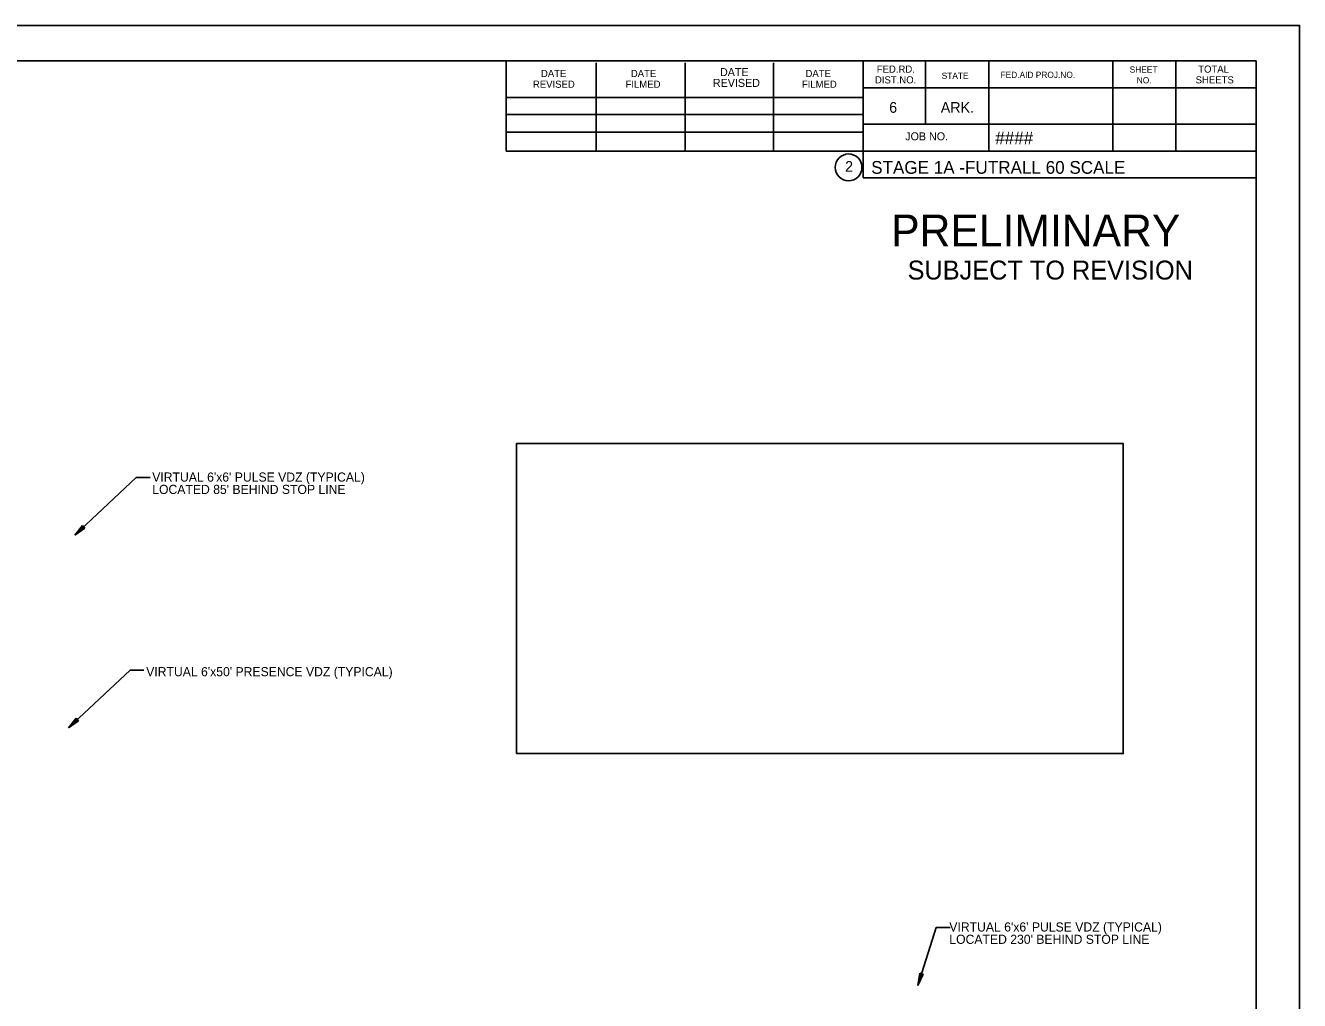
# Model space of a CAD drawing. Extents: x 662183 to 663183, y 642099 to 642739.
# Drawn here: x 662763.4 to 663182.7, y 642418.5 to 642739.3 of the extents above; entities that cross this region are included whole.
import ezdxf

# ---------------------------------------------------------------- set-up
doc = ezdxf.new("R2010")
doc.units = 0
for name, color, linetype in [('R_Border', 7, 'Continuous'), ('R_Border Prem', 7, 'Continuous'), ('R_No Plot', 7, 'Continuous'), ('T_Drafting', 7, 'Continuous')]:
    doc.layers.add(name, color=color, linetype=linetype)

msp = doc.modelspace()

# ---------------------------------------------------------------- linework, layer by layer
at = {"layer": 'R_Border'}
for p, q in [((662219.86, 642727.62), (663168.4, 642727.62)), ((662921.62, 642697.98), (662921.62, 642727.62)), ((662951.2, 642697.98), (662951.2, 642727.02)), ((662980.48, 642697.98), (662980.48, 642727.02)), ((663009.52, 642697.98), (663009.52, 642727.02)), ((663039.1, 642727.62), (663039.1, 642689.22)), ((663059.62, 642727.62), (663059.62, 642706.8)), ((663080.44, 642727.62), (663080.44, 642697.98)), ((663121.18, 642727.62), (663121.18, 642697.98)), ((663142, 642727.62), (663142, 642697.98)), ((663168.4, 642111.24), (663168.4, 642727.62)), ((663168.4, 642718.8), (663039.1, 642718.8)), ((663168.4, 642718.86), (663168.4, 642718.86)), ((662921.62, 642715.56), (663039.1, 642715.56)), ((662921.62, 642709.98), (663039.1, 642709.98)), ((663168.4, 642706.8), (663039.1, 642706.8)), ((663047.98, 642706.8), (663168.4, 642706.8)), ((662921.62, 642697.98), (662921.62, 642704.16)), ((662921.62, 642704.16), (663039.1, 642704.16)), ((663168.4, 642697.98), (662921.62, 642697.98)), ((663039.1, 642689.22), (663168.4, 642689.22))]:
    msp.add_line(p, q, dxfattribs=at)
msp.add_circle((663034.26, 642692.62), 4.4, dxfattribs=at)
at = {"layer": 'R_No Plot'}
msp.add_line((662182.66, 642739.3), (663182.66, 642739.3), dxfattribs=at)
msp.add_lwpolyline([(662182.64, 642739.3), (663182.66, 642739.3), (663182.66, 642099.29), (662182.64, 642099.29)], close=True, dxfattribs=at)
at = {"layer": 'T_Drafting'}
for p, q in [((662799.85, 642590.61), (662779.59, 642571.66)), ((662804.44, 642590.61), (662799.85, 642590.61)), ((662782.1, 642574.83), (662779.59, 642571.66)), ((662782.92, 642573.95), (662779.59, 642571.66)), ((662782.17, 642574.76), (662780.08, 642572.11)), ((662782.85, 642574.03), (662780.08, 642572.11)), ((662782.24, 642574.68), (662780.58, 642572.58)), ((662782.78, 642574.1), (662780.58, 642572.58)), ((662782.31, 642574.61), (662781.07, 642573.04)), ((662782.71, 642574.17), (662781.07, 642573.04)), ((662782.38, 642574.53), (662781.56, 642573.5)), ((662782.64, 642574.25), (662781.56, 642573.5)), ((662782.45, 642574.46), (662782.05, 642573.96)), ((662782.58, 642574.32), (662782.05, 642573.96)), ((662782.92, 642573.95), (662782.1, 642574.83)), ((662797.79, 642527.14), (662777.53, 642508.19)), ((662802.38, 642527.14), (662797.79, 642527.14)), ((662780.04, 642511.36), (662777.53, 642508.19)), ((662780.86, 642510.48), (662777.53, 642508.19)), ((662780.11, 642511.29), (662778.02, 642508.65)), ((662780.79, 642510.56), (662778.02, 642508.65)), ((662780.18, 642511.21), (662778.52, 642509.12)), ((662780.72, 642510.63), (662778.52, 642509.12)), ((662780.25, 642511.14), (662779.01, 642509.57)), ((662780.65, 642510.71), (662779.01, 642509.57)), ((662780.32, 642511.07), (662779.5, 642510.03)), ((662780.58, 642510.78), (662779.5, 642510.03)), ((662780.39, 642510.99), (662779.99, 642510.49)), ((662780.52, 642510.85), (662779.99, 642510.49)), ((662780.86, 642510.48), (662780.04, 642511.36)), ((663063.07, 642442.53), (663057.07, 642423.5)), ((663067.66, 642442.53), (663063.07, 642442.53)), ((663057.7, 642427.5), (663057.07, 642423.5)), ((663058.84, 642427.14), (663057.07, 642423.5)), ((663057.79, 642427.47), (663057.27, 642424.14)), ((663058.75, 642427.17), (663057.27, 642424.14)), ((663057.89, 642427.44), (663057.47, 642424.8)), ((663058.65, 642427.2), (663057.47, 642424.8)), ((663057.98, 642427.41), (663057.67, 642425.43)), ((663058.55, 642427.23), (663057.67, 642425.43)), ((663058.84, 642427.14), (663057.7, 642427.5)), ((663058.08, 642427.38), (663057.88, 642426.08)), ((663058.45, 642427.26), (663057.88, 642426.08)), ((663058.18, 642427.35), (663058.08, 642426.71)), ((663058.36, 642427.29), (663058.08, 642426.71))]:
    msp.add_line(p, q, dxfattribs=at)
msp.add_lwpolyline([(662924.98, 642499.74), (663124.64, 642499.74), (663124.64, 642601.74), (662924.98, 642601.74)], close=True, dxfattribs=at)

# ---------------------------------------------------------------- texts
at = {"layer": 'R_Border'}
for s, height, p in [('DATE', 2.346, (662933.02, 642722.34)), ('DATE', 2.346, (662962.6, 642722.34)), ('DATE', 2.638, (662991.94, 642722.64)), ('DATE', 2.346, (663020.08, 642722.34)), ('DIST.NO.', 2.346, (663042.94, 642720.24)), ('FED.RD.', 2.346, (663043.54, 642723.78)), ('STATE', 2.052, (663064.9, 642721.74)), ('FED.AID PROJ.NO.', 2.052, (663084.28, 642722.04)), ('SHEET', 2.052, (663126.76, 642723.78)), ('SHEETS', 2.346, (663148.48, 642720.24)), ('TOTAL', 2.346, (663149.32, 642723.78)), ('REVISED', 2.346, (662930.38, 642718.8)), ('FILMED', 2.346, (662960.86, 642718.8)), ('REVISED', 2.638, (662989.6, 642719.1)), ('FILMED', 2.346, (663018.88, 642718.8)), ('NO.', 2.052, (663129.1, 642720.24)), ('6', 3.52, (663047.62, 642710.58)), ('ARK.', 3.517, (663064.6, 642710.58)), ('JOB NO.', 2.638, (663052.9, 642701.52)), ('####', 4.2, (663082.53, 642700.19)), ('2', 3.52, (663033.11, 642691.16)), ('STAGE 1A -FUTRALL 60 SCALE', 4.2, (663041.69, 642690.51))]:
    msp.add_text(s, height=height, rotation=360, dxfattribs=at).set_placement(p)
at = {"layer": 'R_Border Prem'}
for s, height, p in [('PRELIMINARY', 10.5, (663048.26, 642666.61)), ('SUBJECT TO REVISION', 6.2253, (663053.68, 642655.72))]:
    msp.add_text(s, height=height, rotation=360, dxfattribs=at).set_placement(p)
at = {"layer": 'T_Drafting'}
for s, p in [("VIRTUAL 6'x6' PULSE VDZ (TYPICAL)", (662805.09, 642589.23)), ("LOCATED 85' BEHIND STOP LINE", (662805.09, 642585.17)), ("VIRTUAL 6'x50' PRESENCE VDZ (TYPICAL)", (662803.1, 642525.2)), ("VIRTUAL 6'x6' PULSE VDZ (TYPICAL)", (663067.41, 642441.21)), ("LOCATED 230' BEHIND STOP LINE", (663067.41, 642437.15))]:
    msp.add_text(s, height=3, dxfattribs=at).set_placement(p)

doc.saveas('drawing.dxf')
